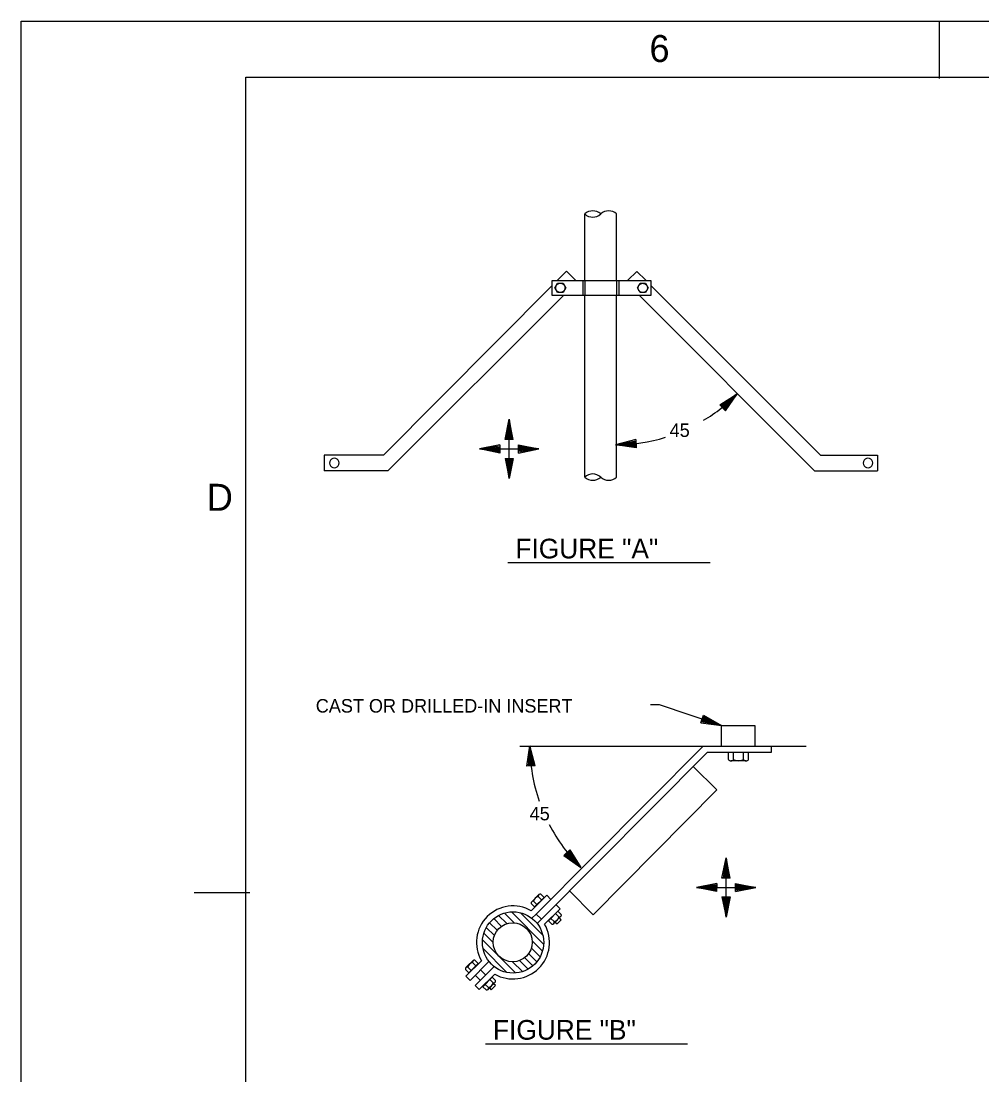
# Model space of a CAD drawing. Extents: x 10040.55 to 10045.84, y 10033.26 to 10035.76.
# Drawn here: x 10040.547 to 10041.26, y 10034.974 to 10035.756 of the extents above; entities that cross this region are included whole.
import ezdxf

# ---------------------------------------------------------------- set-up
doc = ezdxf.new("R2010")
doc.units = 0
doc.layers.add('Level 1', color=7, linetype='Continuous')
doc.layers.add('Level 2', color=7, linetype='Continuous')

msp = doc.modelspace()

# ---------------------------------------------------------------- linework, layer by layer
at = {"layer": 'Level 1'}
for p, q in [((10040.54697, 10033.25552), (10040.54697, 10035.75552)), ((10040.54697, 10035.75552), (10044.04697, 10035.75552)), ((10041.22792, 10035.75552), (10041.22792, 10035.71285)), ((10040.71364, 10033.29719), (10040.71364, 10035.71385)), ((10040.71364, 10035.71385), (10044.0053, 10035.71385)), ((10040.67536, 10035.10939), (10040.71659, 10035.10939))]:
    msp.add_line(p, q, dxfattribs=at)
at = {"layer": 'Level 2'}
for p, q in [((10040.96508, 10035.56317), (10040.96508, 10035.61247)), ((10040.98852, 10035.56317), (10040.98852, 10035.61247)), ((10040.95142, 10035.57016), (10040.94451, 10035.56325)), ((10040.95142, 10035.57016), (10040.95833, 10035.56325)), ((10040.99691, 10035.56329), (10041.00353, 10035.56992)), ((10041.01015, 10035.56329), (10041.00353, 10035.56992)), ((10040.94448, 10035.56321), (10040.94451, 10035.56325)), ((10040.96345, 10035.5632), (10040.96345, 10035.5521)), ((10040.96508, 10035.56317), (10040.96508, 10035.55204)), ((10040.98852, 10035.56317), (10040.98852, 10035.55204)), ((10040.99018, 10035.56329), (10040.99018, 10035.55204)), ((10041.01022, 10035.56322), (10041.01019, 10035.56325)), ((10040.81577, 10035.43367), (10040.94069, 10035.55947)), ((10041.13978, 10035.43354), (10041.01398, 10035.55947)), ((10040.94924, 10035.55206), (10040.81896, 10035.42199)), ((10040.96508, 10035.41738), (10040.96508, 10035.55211)), ((10040.98852, 10035.41738), (10040.98852, 10035.55211)), ((10041.13543, 10035.42199), (10041.00549, 10035.55204)), ((10041.06513, 10035.47093), (10041.07808, 10035.47914)), ((10041.07808, 10035.47914), (10041.06568, 10035.47032)), ((10041.07808, 10035.47914), (10041.06618, 10035.46979)), ((10041.07808, 10035.47914), (10041.0667, 10035.46926)), ((10041.06721, 10035.46871), (10041.07808, 10035.47914)), ((10041.07808, 10035.47914), (10041.06771, 10035.46821)), ((10041.07808, 10035.47914), (10041.06815, 10035.46771)), ((10041.07808, 10035.47914), (10041.06875, 10035.46711)), ((10041.06928, 10035.46656), (10041.07808, 10035.47914)), ((10041.06928, 10035.46656), (10041.06513, 10035.47093)), ((10040.90584, 10035.44518), (10040.90886, 10035.46022)), ((10040.90886, 10035.46022), (10040.90666, 10035.44517)), ((10040.90886, 10035.46022), (10040.90739, 10035.44516)), ((10040.90886, 10035.46022), (10040.90813, 10035.44517)), ((10040.90886, 10035.41623), (10040.90886, 10035.46022)), ((10040.90889, 10035.44516), (10040.90886, 10035.46022)), ((10040.91186, 10035.44517), (10040.90886, 10035.46022)), ((10040.90886, 10035.46022), (10040.91026, 10035.44515)), ((10040.90886, 10035.46022), (10040.90958, 10035.44517)), ((10040.90886, 10035.46022), (10040.9111, 10035.44517)), ((10040.91186, 10035.44517), (10040.90584, 10035.44518)), ((10041.00276, 10035.44516), (10040.98789, 10035.44136)), ((10040.98789, 10035.44136), (10041.0028, 10035.44439)), ((10040.98789, 10035.44136), (10041.00286, 10035.44355)), ((10041.00276, 10035.44516), (10041.00307, 10035.43914)), ((10040.90193, 10035.44122), (10040.88688, 10035.43822)), ((10040.88688, 10035.43822), (10040.90193, 10035.44046)), ((10040.88688, 10035.43822), (10040.90195, 10035.43961)), ((10040.88688, 10035.43822), (10040.90193, 10035.43894)), ((10040.90194, 10035.43824), (10040.88688, 10035.43822)), ((10040.88688, 10035.43822), (10040.93086, 10035.43822)), ((10040.90192, 10035.4352), (10040.88688, 10035.43822)), ((10040.88688, 10035.43822), (10040.90194, 10035.43674)), ((10040.88688, 10035.43822), (10040.90193, 10035.43601)), ((10040.88688, 10035.43822), (10040.90193, 10035.43748)), ((10040.90193, 10035.44122), (10040.90192, 10035.4352)), ((10040.93086, 10035.43822), (10040.91579, 10035.43682)), ((10040.93086, 10035.43822), (10040.9158, 10035.4397)), ((10040.9158, 10035.4382), (10040.93086, 10035.43822)), ((10040.91581, 10035.43522), (10040.91582, 10035.44124)), ((10040.93086, 10035.43822), (10040.91581, 10035.44043)), ((10040.93086, 10035.43822), (10040.91581, 10035.43896)), ((10040.91581, 10035.43522), (10040.93086, 10035.43822)), ((10040.93086, 10035.43822), (10040.91581, 10035.4375)), ((10040.93086, 10035.43822), (10040.91581, 10035.43598)), ((10040.91582, 10035.44124), (10040.93086, 10035.43822)), ((10040.98789, 10035.44136), (10041.00289, 10035.44289)), ((10041.00293, 10035.44218), (10040.98789, 10035.44136)), ((10040.98789, 10035.44136), (10041.00296, 10035.44143)), ((10041.00307, 10035.43914), (10040.98789, 10035.44136)), ((10040.98789, 10035.44136), (10041.00301, 10035.44068)), ((10040.98789, 10035.44136), (10041.00303, 10035.43996)), ((10040.81577, 10035.43367), (10040.77177, 10035.43367)), ((10040.77177, 10035.43367), (10040.77177, 10035.42199)), ((10040.90586, 10035.43128), (10040.91189, 10035.43127)), ((10040.90586, 10035.43128), (10040.90886, 10035.41623)), ((10040.90886, 10035.41623), (10040.90663, 10035.43128)), ((10040.90886, 10035.41623), (10040.90747, 10035.4313)), ((10040.90886, 10035.41623), (10040.90815, 10035.43128)), ((10040.90884, 10035.43129), (10040.90886, 10035.41623)), ((10040.90886, 10035.41623), (10040.91034, 10035.43129)), ((10040.90886, 10035.41623), (10040.91107, 10035.43128)), ((10040.90886, 10035.41623), (10040.9096, 10035.43128)), ((10040.91189, 10035.43127), (10040.90886, 10035.41623)), ((10041.13978, 10035.43354), (10041.18202, 10035.43354)), ((10041.18202, 10035.43354), (10041.18202, 10035.42199)), ((10040.81896, 10035.42199), (10040.77177, 10035.42199)), ((10041.13543, 10035.42199), (10041.18203, 10035.42199)), ((10040.90799, 10035.35406), (10041.05792, 10035.35406)), ((10041.0511, 10035.23516), (10041.05303, 10035.24086)), ((10041.05303, 10035.24086), (10041.06633, 10035.23321)), ((10041.0511, 10035.23516), (10041.06633, 10035.23321)), ((10041.06633, 10035.23321), (10041.05135, 10035.23588)), ((10041.06633, 10035.23321), (10041.05159, 10035.23669)), ((10041.06633, 10035.23321), (10041.05183, 10035.23731)), ((10041.05204, 10035.23798), (10041.06633, 10035.23321)), ((10041.06633, 10035.23321), (10041.05229, 10035.2387)), ((10041.06633, 10035.23321), (10041.05252, 10035.23941)), ((10041.06633, 10035.23321), (10041.05276, 10035.24008)), ((10040.91683, 10035.2179), (10041.12922, 10035.2179)), ((10040.92207, 10035.20298), (10040.9243, 10035.21817)), ((10040.9243, 10035.21817), (10040.9229, 10035.20302)), ((10040.9243, 10035.21817), (10040.92361, 10035.20304)), ((10040.92511, 10035.20313), (10040.9243, 10035.21817)), ((10040.92809, 10035.20329), (10040.9243, 10035.21817)), ((10040.9243, 10035.21817), (10040.92649, 10035.20319)), ((10040.9243, 10035.21817), (10040.92436, 10035.20309)), ((10040.9243, 10035.21817), (10040.92582, 10035.20317)), ((10040.9243, 10035.21817), (10040.92732, 10035.20325)), ((10040.92892, 10035.09336), (10041.05273, 10035.21775)), ((10041.05273, 10035.21775), (10041.10326, 10035.2179)), ((10041.10326, 10035.2179), (10041.10326, 10035.21323)), ((10040.93278, 10035.08956), (10041.05586, 10035.21323)), ((10041.10326, 10035.21323), (10041.05586, 10035.21323)), ((10041.08647, 10035.21322), (10041.07154, 10035.21322)), ((10041.07155, 10035.20801), (10041.07154, 10035.21322)), ((10041.07526, 10035.20801), (10041.07526, 10035.21323)), ((10041.08278, 10035.20802), (10041.08278, 10035.21322)), ((10041.08645, 10035.20801), (10041.08647, 10035.21322)), ((10040.92809, 10035.20329), (10040.92207, 10035.20298)), ((10041.06282, 10035.18539), (10041.04541, 10035.20272)), ((10041.08459, 10035.2069), (10041.07342, 10035.2069)), ((10040.97133, 10035.09285), (10041.06282, 10035.18539)), ((10040.9495, 10035.13677), (10040.95386, 10035.14093)), ((10040.95165, 10035.13884), (10040.96207, 10035.12797)), ((10040.96207, 10035.12797), (10040.9522, 10035.13935)), ((10040.96207, 10035.12797), (10040.95273, 10035.13988)), ((10040.96207, 10035.12797), (10040.95326, 10035.14038)), ((10040.95386, 10035.14093), (10040.96207, 10035.12797)), ((10040.9495, 10035.13677), (10040.96207, 10035.12797)), ((10040.96207, 10035.12797), (10040.95005, 10035.1373)), ((10040.96207, 10035.12797), (10040.95065, 10035.13791)), ((10040.96207, 10035.12797), (10040.95115, 10035.13834)), ((10041.06672, 10035.11999), (10041.06974, 10035.13503)), ((10041.06974, 10035.13503), (10041.06753, 10035.11998)), ((10041.06974, 10035.13503), (10041.06826, 10035.11997)), ((10041.06974, 10035.13503), (10041.069, 10035.11998)), ((10041.06974, 10035.09104), (10041.06974, 10035.13503)), ((10041.06976, 10035.11997), (10041.06974, 10035.13503)), ((10041.07274, 10035.11998), (10041.06974, 10035.13503)), ((10041.06974, 10035.13503), (10041.07114, 10035.11996)), ((10041.06974, 10035.13503), (10041.07046, 10035.11998)), ((10041.06974, 10035.13503), (10041.07198, 10035.11998)), ((10041.0628, 10035.11603), (10041.04775, 10035.11303)), ((10041.04775, 10035.11303), (10041.0628, 10035.11527)), ((10041.0628, 10035.11603), (10041.06279, 10035.11001)), ((10041.07274, 10035.11998), (10041.06672, 10035.11999)), ((10041.07669, 10035.11003), (10041.0767, 10035.11605)), ((10041.09174, 10035.11303), (10041.07669, 10035.11524)), ((10041.0767, 10035.11605), (10041.09174, 10035.11303)), ((10040.92564, 10035.10254), (10040.93091, 10035.10781)), ((10040.9323, 10035.10817), (10040.93476, 10035.10572)), ((10040.97133, 10035.09285), (10040.95361, 10035.11049)), ((10041.04775, 10035.11303), (10041.06282, 10035.11443)), ((10041.04775, 10035.11303), (10041.0628, 10035.11375)), ((10041.06281, 10035.11305), (10041.04775, 10035.11303)), ((10041.04775, 10035.11303), (10041.09174, 10035.11303)), ((10041.06279, 10035.11001), (10041.04775, 10035.11303)), ((10041.04775, 10035.11303), (10041.06281, 10035.11155)), ((10041.04775, 10035.11303), (10041.0628, 10035.11082)), ((10041.04775, 10035.11303), (10041.0628, 10035.11229)), ((10041.09174, 10035.11303), (10041.07667, 10035.11164)), ((10041.09174, 10035.11303), (10041.07668, 10035.11451)), ((10041.07668, 10035.11301), (10041.09174, 10035.11303)), ((10041.09174, 10035.11303), (10041.07669, 10035.11377)), ((10041.07669, 10035.11003), (10041.09174, 10035.11303)), ((10041.09174, 10035.11303), (10041.07669, 10035.11231)), ((10041.09174, 10035.11303), (10041.07669, 10035.11079)), ((10040.92528, 10035.10115), (10040.92773, 10035.09869)), ((10040.9253, 10035.09577), (10040.93679, 10035.10726)), ((10040.92702, 10035.10288), (10040.92947, 10035.10043)), ((10040.92773, 10035.09869), (10040.93476, 10035.10572)), ((10040.93055, 10035.10642), (10040.93301, 10035.10396)), ((10040.93679, 10035.10726), (10040.93978, 10035.10427)), ((10040.94671, 10035.09734), (10040.94365, 10035.10042)), ((10041.06674, 10035.10609), (10041.07276, 10035.10608)), ((10041.06674, 10035.10609), (10041.06974, 10035.09104)), ((10041.06974, 10035.09104), (10041.0675, 10035.10609)), ((10041.06974, 10035.09104), (10041.06834, 10035.10611)), ((10041.06974, 10035.09104), (10041.06902, 10035.10609)), ((10041.06972, 10035.1061), (10041.06974, 10035.09104)), ((10041.06974, 10035.09104), (10041.07122, 10035.1061)), ((10041.06974, 10035.09104), (10041.07195, 10035.10609)), ((10041.06974, 10035.09104), (10041.07048, 10035.10609)), ((10041.07276, 10035.10608), (10041.06974, 10035.09104)), ((10040.90723, 10035.08627), (10040.90113, 10035.09238)), ((10040.91265, 10035.0869), (10040.90541, 10035.09413)), ((10040.9345, 10035.07108), (10040.91057, 10035.09501)), ((10040.93388, 10035.07775), (10040.91721, 10035.0944)), ((10040.9258, 10035.09023), (10040.92892, 10035.09336)), ((10040.92892, 10035.09336), (10040.93278, 10035.08956)), ((10040.93522, 10035.08585), (10040.94671, 10035.09734)), ((10040.93817, 10035.0884), (10040.94509, 10035.09553)), ((10040.94205, 10035.08636), (10040.94725, 10035.09171)), ((10040.94585, 10035.09133), (10040.94336, 10035.09376)), ((10040.94758, 10035.09311), (10040.94509, 10035.09553)), ((10040.90013, 10035.08131), (10040.89445, 10035.08699)), ((10040.90321, 10035.08427), (10040.8975, 10035.08998)), ((10040.92965, 10035.08641), (10040.93278, 10035.08956)), ((10040.94067, 10035.08599), (10040.93817, 10035.0884)), ((10040.94236, 10035.08775), (10040.93989, 10035.09017)), ((10040.89711, 10035.07225), (10040.89016, 10035.07922)), ((10040.89798, 10035.07743), (10040.89198, 10035.08343)), ((10040.91366, 10035.04968), (10040.88917, 10035.07417)), ((10040.93361, 10035.06591), (10040.926, 10035.07354)), ((10040.90724, 10035.05006), (10040.88955, 10035.06775)), ((10040.92648, 10035.05496), (10040.92042, 10035.06102)), ((10040.92946, 10035.05801), (10040.92338, 10035.0641)), ((10040.93186, 10035.06165), (10040.92538, 10035.06813)), ((10040.87684, 10035.05364), (10040.88211, 10035.05891)), ((10040.87691, 10035.04733), (10040.88832, 10035.05875)), ((10040.87823, 10035.05397), (10040.88068, 10035.05152)), ((10040.87894, 10035.04978), (10040.88597, 10035.05681)), ((10040.87988, 10035.04422), (10040.8939, 10035.05824)), ((10040.88176, 10035.05751), (10040.88422, 10035.05505)), ((10040.88351, 10035.05926), (10040.88597, 10035.05681)), ((10040.88367, 10035.04044), (10040.89769, 10035.05445)), ((10040.91871, 10035.05067), (10040.91136, 10035.05801)), ((10040.92292, 10035.05249), (10040.91652, 10035.05888)), ((10040.87649, 10035.05224), (10040.87894, 10035.04978)), ((10040.87681, 10035.04728), (10040.87988, 10035.04422)), ((10040.88368, 10035.04802), (10040.88747, 10035.04424)), ((10040.89822, 10035.04886), (10040.88673, 10035.03738)), ((10040.88768, 10035.05202), (10040.89147, 10035.04824)), ((10040.88938, 10035.03949), (10040.8963, 10035.04663)), ((10040.89706, 10035.04243), (10040.89457, 10035.04485)), ((10040.89879, 10035.04421), (10040.8963, 10035.04663)), ((10040.88673, 10035.03738), (10040.88367, 10035.04044)), ((10040.89188, 10035.03708), (10040.88938, 10035.03949)), ((10040.89357, 10035.03884), (10040.89109, 10035.04126)), ((10040.89326, 10035.03746), (10040.89846, 10035.0428)), ((10040.89135, 10034.99719), (10041.04128, 10034.99719))]:
    msp.add_line(p, q, dxfattribs=at)
for points in [[(10041.01391, 10035.55205), (10040.94073, 10035.55205), (10040.94073, 10035.5632), (10041.01391, 10035.5632)], [(10040.95092, 10035.55777), (10040.9489, 10035.55426), (10040.94486, 10035.55426), (10040.94286, 10035.55777), (10040.94486, 10035.56122), (10040.9489, 10035.56122)], [(10040.95033, 10035.55777), (10040.95033, 10035.55753), (10040.95029, 10035.55731), (10040.95026, 10035.55709), (10040.95023, 10035.55688), (10040.95016, 10035.55667), (10040.95009, 10035.55646), (10040.95001, 10035.55628), (10040.9499, 10035.55605), (10040.94979, 10035.55588), (10040.94968, 10035.55571), (10040.94954, 10035.55553), (10040.9494, 10035.55538), (10040.94923, 10035.55523), (10040.94908, 10035.55507), (10040.9489, 10035.55494), (10040.94873, 10035.55481), (10040.94855, 10035.55472), (10040.94834, 10035.55461), (10040.94816, 10035.55451), (10040.94794, 10035.55447), (10040.94774, 10035.55438), (10040.94752, 10035.55435), (10040.94731, 10035.55432), (10040.94708, 10035.5543), (10040.9469, 10035.5543), (10040.94667, 10035.5543), (10040.94644, 10035.55432), (10040.94622, 10035.55435), (10040.94601, 10035.55438), (10040.94581, 10035.55447), (10040.94558, 10035.55451), (10040.94541, 10035.55461), (10040.94521, 10035.55472), (10040.94501, 10035.55481), (10040.94485, 10035.55494), (10040.94467, 10035.55507), (10040.94452, 10035.55523), (10040.94436, 10035.55538), (10040.9442, 10035.55553), (10040.94406, 10035.55571), (10040.94397, 10035.55588), (10040.94385, 10035.55605), (10040.94374, 10035.55628), (10040.94366, 10035.55646), (10040.94359, 10035.55667), (10040.94352, 10035.55688), (10040.94349, 10035.55709), (10040.94347, 10035.55731), (10040.94343, 10035.55753), (10040.94343, 10035.55777), (10040.94343, 10035.55796), (10040.94347, 10035.55817), (10040.94349, 10035.55839), (10040.94352, 10035.55861), (10040.94359, 10035.55881), (10040.94366, 10035.55902), (10040.94374, 10035.5592), (10040.94385, 10035.55941), (10040.94397, 10035.5596), (10040.94406, 10035.55977), (10040.9442, 10035.55996), (10040.94436, 10035.5601), (10040.94452, 10035.56026), (10040.94467, 10035.56041), (10040.94485, 10035.56054), (10040.94501, 10035.56067), (10040.94521, 10035.56077), (10040.94541, 10035.56086), (10040.94558, 10035.56097), (10040.94581, 10035.56102), (10040.94601, 10035.56108), (10040.94622, 10035.56114), (10040.94644, 10035.56117), (10040.94667, 10035.56119), (10040.9469, 10035.56119), (10040.94708, 10035.56119), (10040.94731, 10035.56117), (10040.94752, 10035.56114), (10040.94774, 10035.56108), (10040.94794, 10035.56102), (10040.94816, 10035.56097), (10040.94834, 10035.56086), (10040.94855, 10035.56077), (10040.94873, 10035.56067), (10040.9489, 10035.56054), (10040.94908, 10035.56041), (10040.94923, 10035.56026), (10040.9494, 10035.5601), (10040.94954, 10035.55996), (10040.94968, 10035.55977), (10040.94979, 10035.5596), (10040.9499, 10035.55941), (10040.95001, 10035.5592), (10040.95009, 10035.55902), (10040.95016, 10035.55881), (10040.95023, 10035.55861), (10040.95026, 10035.55839), (10040.95029, 10035.55817)], [(10041.01205, 10035.55767), (10041.01003, 10035.55416), (10041.006, 10035.55416), (10041.004, 10035.55767), (10041.006, 10035.56111), (10041.01003, 10035.56111)], [(10041.01147, 10035.55767), (10041.01147, 10035.55743), (10041.01143, 10035.55721), (10041.0114, 10035.55699), (10041.01136, 10035.55677), (10041.01129, 10035.55656), (10041.01123, 10035.55635), (10041.01115, 10035.55618), (10041.01103, 10035.55595), (10041.01093, 10035.55577), (10041.01081, 10035.5556), (10041.01068, 10035.55543), (10041.01053, 10035.55527), (10041.01036, 10035.55513), (10041.01022, 10035.55497), (10041.01003, 10035.55483), (10041.00986, 10035.55471), (10041.00969, 10035.55461), (10041.00948, 10035.55451), (10041.00929, 10035.55441), (10041.00907, 10035.55436), (10041.00888, 10035.55427), (10041.00866, 10035.55425), (10041.00845, 10035.55422), (10041.00822, 10035.5542), (10041.00803, 10035.5542), (10041.0078, 10035.5542), (10041.00757, 10035.55422), (10041.00735, 10035.55425), (10041.00715, 10035.55427), (10041.00695, 10035.55436), (10041.00672, 10035.55441), (10041.00654, 10035.55451), (10041.00634, 10035.55461), (10041.00615, 10035.55471), (10041.00599, 10035.55483), (10041.0058, 10035.55497), (10041.00566, 10035.55513), (10041.0055, 10035.55527), (10041.00533, 10035.55543), (10041.0052, 10035.5556), (10041.0051, 10035.55577), (10041.00499, 10035.55595), (10041.00488, 10035.55618), (10041.00479, 10035.55635), (10041.00473, 10035.55656), (10041.00466, 10035.55677), (10041.00463, 10035.55699), (10041.0046, 10035.55721), (10041.00456, 10035.55743), (10041.00456, 10035.55767), (10041.00456, 10035.55785), (10041.0046, 10035.55806), (10041.00463, 10035.55828), (10041.00466, 10035.55851), (10041.00473, 10035.55871), (10041.00479, 10035.55892), (10041.00488, 10035.55909), (10041.00499, 10035.5593), (10041.0051, 10035.5595), (10041.0052, 10035.55967), (10041.00533, 10035.55985), (10041.0055, 10035.56), (10041.00566, 10035.56016), (10041.0058, 10035.5603), (10041.00599, 10035.56044), (10041.00615, 10035.56056), (10041.00634, 10035.56067), (10041.00654, 10035.56076), (10041.00672, 10035.56086), (10041.00695, 10035.56092), (10041.00715, 10035.56098), (10041.00735, 10035.56103), (10041.00757, 10035.56106), (10041.0078, 10035.56108), (10041.00803, 10035.56108), (10041.00822, 10035.56108), (10041.00845, 10035.56106), (10041.00866, 10035.56103), (10041.00888, 10035.56098), (10041.00907, 10035.56092), (10041.00929, 10035.56086), (10041.00948, 10035.56076), (10041.00969, 10035.56067), (10041.00986, 10035.56056), (10041.01003, 10035.56044), (10041.01022, 10035.5603), (10041.01036, 10035.56016), (10041.01053, 10035.56), (10041.01068, 10035.55985), (10041.01081, 10035.55967), (10041.01093, 10035.5595), (10041.01103, 10035.5593), (10041.01115, 10035.55909), (10041.01123, 10035.55892), (10041.01129, 10035.55871), (10041.01136, 10035.55851), (10041.0114, 10035.55828), (10041.01143, 10035.55806)], [(10040.77922, 10035.43143), (10040.77811, 10035.43123), (10040.77711, 10035.43071), (10040.77633, 10035.42991), (10040.77583, 10035.42891), (10040.77568, 10035.42779), (10040.77586, 10035.42669), (10040.77639, 10035.4257), (10040.77719, 10035.42492), (10040.77819, 10035.42442), (10040.7793, 10035.42425), (10040.78041, 10035.42444), (10040.7814, 10035.42496), (10040.78219, 10035.42576), (10040.78268, 10035.42677), (10040.78284, 10035.42789), (10040.78266, 10035.42899), (10040.78214, 10035.42998), (10040.78133, 10035.43076), (10040.78032, 10035.43126)], [(10041.17497, 10035.43143), (10041.17386, 10035.43123), (10041.17288, 10035.43071), (10041.17208, 10035.42991), (10041.17159, 10035.42891), (10041.17143, 10035.42779), (10041.17161, 10035.42669), (10041.17214, 10035.4257), (10041.17294, 10035.42492), (10041.17395, 10035.42442), (10041.17505, 10035.42425), (10041.17616, 10035.42444), (10041.17716, 10035.42496), (10041.17794, 10035.42576), (10041.17844, 10035.42677), (10041.17859, 10035.42789), (10041.17841, 10035.42899), (10041.17789, 10035.42998), (10041.17708, 10035.43076), (10041.17608, 10035.43126)]]:
    msp.add_lwpolyline(points, close=True, dxfattribs=at)
for points in [[(10041.0138, 10035.24871), (10041.02015, 10035.24871), (10041.06633, 10035.23321)], [(10041.06633, 10035.218), (10041.06633, 10035.23321), (10041.09111, 10035.23321), (10041.09111, 10035.2179)], [(10040.94307, 10035.08746), (10040.94446, 10035.08608), (10040.94755, 10035.08919), (10040.94618, 10035.09056)], [(10040.89428, 10035.03856), (10040.89567, 10035.03719), (10040.89876, 10035.04029), (10040.89739, 10035.04167)]]:
    msp.add_lwpolyline(points, dxfattribs=at)
for centre, radius in [((10040.91181, 10035.07232), 0.02272), ((10040.91157, 10035.07247), 0.01446)]:
    msp.add_circle(centre, radius, dxfattribs=at)
for centre, radius, start, end in [((10040.97094, 10035.60641), 0.00843, 45.9775, 134.02119), ((10040.97094, 10035.61853), 0.00843, 225.97881, 314.0225), ((10040.98266, 10035.60641), 0.00843, 45.97881, 134.0225), ((10040.98789, 10035.56795), 0.12658, 301.03023, 315.44091), ((10040.98789, 10035.56795), 0.12658, 270, 287.02996), ((10040.97094, 10035.41131), 0.00843, 45.9775, 134.02119), ((10040.97094, 10035.42344), 0.00843, 225.97881, 314.0225), ((10040.98266, 10035.42344), 0.00843, 225.9775, 314.02119), ((10041.05089, 10035.21817), 0.12658, 180, 198.96664), ((10041.07341, 10035.20901), 0.00211, 208.34206, 331.66132), ((10041.07902, 10035.21379), 0.00689, 237.03159, 302.96841), ((10041.08461, 10035.20899), 0.00209, 207.91313, 332.05962), ((10041.05089, 10035.21817), 0.12658, 207.45917, 225.44342), ((10040.9319, 10035.10682), 0.00141, 73.34206, 196.66132), ((10040.92661, 10035.10155), 0.00139, 72.91313, 197.05962), ((10040.93151, 10035.10192), 0.00459, 102.03159, 167.96841), ((10040.91176, 10035.07232), 0.02708, 60.01092, 209.9726), ((10040.94624, 10035.09269), 0.00141, 254.18391, 17.50317), ((10040.91176, 10035.07232), 0.02708, 239.97776, 29.98899), ((10040.94105, 10035.08732), 0.00139, 253.78561, 17.9321), ((10040.94135, 10035.09223), 0.00459, 282.87682, 348.81364), ((10040.87782, 10035.05264), 0.00139, 72.91313, 197.05962), ((10040.88272, 10035.05302), 0.00459, 102.03159, 167.96841), ((10040.88311, 10035.05791), 0.00141, 73.34206, 196.66132), ((10040.89226, 10035.03842), 0.00139, 253.78561, 17.9321), ((10040.89256, 10035.04332), 0.00459, 282.87682, 348.81364), ((10040.89745, 10035.04379), 0.00141, 254.18391, 17.50317)]:
    msp.add_arc(centre, radius, start, end, dxfattribs=at)

# ---------------------------------------------------------------- texts
at = {"layer": 'Level 1'}
for s, p in [('6', (10041.01297, 10035.72519)), ('D', (10040.68472, 10035.39241))]:
    msp.add_text(s, height=0.02, dxfattribs=at).set_placement(p)
at = {"layer": 'Level 2'}
for s, height, p in [('45', 0.01, (10041.02794, 10035.44714)), ('FIGURE "A"', 0.014583, (10040.91356, 10035.35709)), ('CAST OR DRILLED-IN INSERT', 0.01001, (10040.76551, 10035.24278)), ('45', 0.01, (10040.92413, 10035.16286)), ('FIGURE "B"', 0.014583, (10040.89693, 10035.00022))]:
    msp.add_text(s, height=height, dxfattribs=at).set_placement(p)

doc.saveas('drawing.dxf')
